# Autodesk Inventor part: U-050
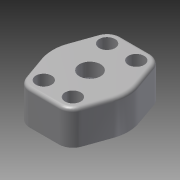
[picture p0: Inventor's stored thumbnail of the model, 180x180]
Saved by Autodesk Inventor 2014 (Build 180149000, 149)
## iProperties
Created: 2011-01
Part Number: U-050
Document SubType Name: Modeling
Designer: deckm
Density: 7.85 g/cm^3
Material: Steel
Description: FLARED FLANGE SAE WITH CLEARANCE HOLES
Mass: 259.498 g
Surface Area: 100.719 cm^2
Volume: 33.0571 cm^3
Appearance: Steel
Author: deckm
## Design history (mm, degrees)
sketch "Sketch2"
  geometry: L1 (-150, 0)-(181, 0) reference; L2 (0, -200)-(0, 246) reference; L3 (-8.763, -27.432)-(8.763, -27.432); L4 (-8.763, 27.432)-(8.763, 27.432); L5 (-16.667, -21.841)-(-21.677, -7.654); L6 (-16.667, 21.841)-(-21.677, 7.654); L7 (16.667, -21.841)-(21.677, -7.654); L8 (16.667, 21.841)-(21.677, 7.654); A1 r 8.382 centre (-8.763, 19.05) between (-8.763, 27.432) and (-16.667, 21.841); A2 r 8.382 centre (-8.763, -19.05) between (-16.667, -21.841) and (-8.763, -27.432); A3 r 8.382 centre (8.763, -19.05) between (8.763, -27.432) and (16.667, -21.841); A4 r 8.382 centre (8.763, 19.05) between (16.667, 21.841) and (8.763, 27.432); A5 r 22.987 centre (-0.001, 0) between (-21.677, 7.654) and (-21.677, -7.654); A6 r 22.987 centre (0.001, 0) between (21.677, -7.654) and (21.677, 7.654); 4 further points
  constraints: 16 end point, 12 point on circle, 12 tangent, 7 point on line, 6 centre point, 4 equal radius, 2 horizontal, 2 perpendicular, 1 parallel, 1 vertical, 4 other
  dimensions: "d1" = 54.864 distance between parallel lines of L4 L3 (derived); "d3" = 109.45 deg angle of L3 L5; "FilletCorners" = 8.382 radius of A1 (derived); "FilletEnds" = 22.987 radius of A5 (derived); "d25" = 17.526 distance of A4.centre A1.centre (derived)
extrude "Extrusion1" new body sketch "Sketch2" distance "d8" = 20.574 (derived); taper "d9" = 0 deg
hole "Hole1" diameter "d12" = 9.525 (derived); stored, may be unused: countersink angle "d16" = 90 deg, drill point angle "d18" = 118 deg; dims "d10" = 10, "d11" = 10, "d13" = 6, "d14" = 4, "d15" = 2, "d17" = 8
pattern_linear "Rectangular Pattern1" dims "d21" = 17.526 (derived), "d24" = 38.1 (derived)
fillet "Fillet1" dims "FilletTop" = 2
sketch "Sketch3"
  geometry: L1 (0, 0)-(-9.525, 0); L2 (-9.525, 0)-(-9.525, 8.18); L3 (-9.525, 8.18)-(-6.35, 12.394); L4 (-6.35, 12.394)-(-6.35, 20.574); L5 (-6.35, 20.574)-(0, 20.574); L6 (0, 20.574)-(0, 0)
  constraints: 12 end point, 3 parallel, 2 perpendicular, 1 horizontal
  dimensions: "d27" = 9.525 distance of L1.start L1.end (derived); "d28" = 37 deg angle of L3 L4; "d29" = 20.574 distance between parallel lines of L5 L1 (derived); "d30" = 6.35 distance of L4.end L5.end (derived)
revolve "Revolution1" sketch "Sketch3" stored, may be unused: angle "d31" = 90 deg
body "Solid1"
